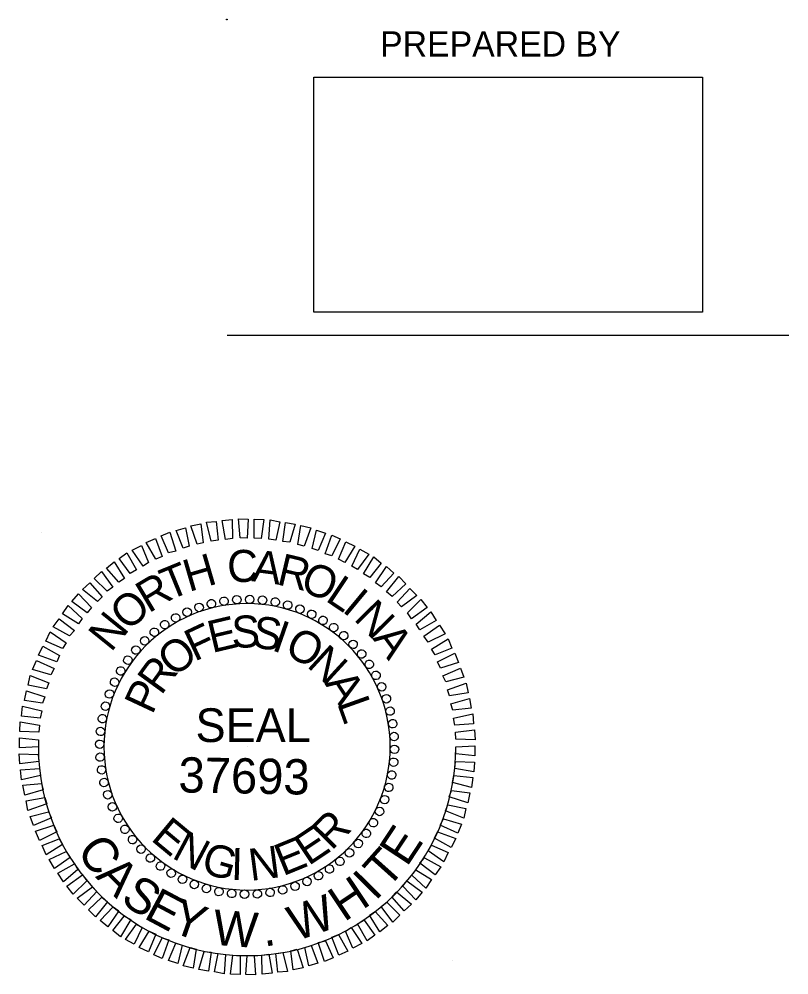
# Model space of a CAD drawing. Extents: x 2.6 to 3.27, y 0.03 to 1.77.
# Drawn here: x 3.0401 to 3.2685, y 1.3982 to 1.6817 of the extents above; entities that cross this region are included whole.
import ezdxf

# ---------------------------------------------------------------- set-up
doc = ezdxf.new("R2010")
doc.units = 0
for name, color, linetype in [('Draft_RDY_Construction_Class_Element', 7, 'Continuous'), ('Scratch_Level_2', 7, 'Continuous'), ('Sheet_PE_Note_CELL', 7, 'Continuous'), ('Sheet_Plan_CELL', 7, 'Continuous')]:
    doc.layers.add(name, color=color, linetype=linetype)

msp = doc.modelspace()

# ---------------------------------------------------------------- linework, layer by layer
at = {"layer": 'Draft_RDY_Construction_Class_Element'}
for p, q in [((3.12757, 1.66449), (3.24285, 1.66449)), ((3.12757, 1.59473), (3.12757, 1.66449)), ((3.24285, 1.66449), (3.24285, 1.59473)), ((3.24285, 1.59473), (3.12757, 1.59473))]:
    msp.add_line(p, q, dxfattribs=at)
msp.add_circle((3.10177, 1.68157), 0.0001, dxfattribs=at)
at = {"layer": 'Scratch_Level_2'}
for p, q in [((3.04683, 1.52933), (3.04683, 1.52933)), ((3.10777, 1.46583), (3.10777, 1.46583)), ((3.16871, 1.40233), (3.16871, 1.40233))]:
    msp.add_line(p, q, dxfattribs=at)
for radius, start, end in [(0.04247, 0, 180), (0.06193, 180, 0), (0.04247, 180, 0)]:
    msp.add_arc((3.10777, 1.46583), radius, start, end, dxfattribs=at)
at = {"layer": 'Sheet_PE_Note_CELL'}
for p, q in [((3.09713, 1.50828), (3.09713, 1.50828)), ((3.10097, 1.50898), (3.10097, 1.50898)), ((3.10472, 1.5095), (3.10472, 1.5095)), ((3.10855, 1.50959), (3.10855, 1.50959)), ((3.11239, 1.50933), (3.11239, 1.50933)), ((3.11614, 1.50872), (3.11614, 1.50872)), ((3.08998, 1.50584), (3.08998, 1.50584)), ((3.09347, 1.50724), (3.09347, 1.50724)), ((3.1198, 1.50794), (3.1198, 1.50794)), ((3.12346, 1.50672), (3.12346, 1.50672)), ((3.08658, 1.5041), (3.08658, 1.5041)), ((3.12694, 1.50515), (3.12694, 1.50515)), ((3.13034, 1.5034), (3.13034, 1.5034)), ((3.08022, 1.49992), (3.08022, 1.49992)), ((3.08327, 1.50209), (3.08327, 1.50209)), ((3.13348, 1.50122), (3.13348, 1.50122)), ((3.07734, 1.4973), (3.07734, 1.4973)), ((3.13653, 1.49887), (3.13653, 1.49887)), ((3.07473, 1.4946), (3.07473, 1.4946)), ((3.13924, 1.49625), (3.13924, 1.49625)), ((3.07238, 1.49155), (3.07238, 1.49155)), ((3.14185, 1.49338), (3.14185, 1.49338)), ((3.0702, 1.48841), (3.0702, 1.48841)), ((3.14403, 1.49033), (3.14403, 1.49033)), ((3.14604, 1.48701), (3.14604, 1.48701)), ((3.06845, 1.48501), (3.06845, 1.48501)), ((3.14778, 1.48361), (3.14778, 1.48361)), ((3.06688, 1.48152), (3.06688, 1.48152)), ((3.14917, 1.48013), (3.14917, 1.48013)), ((3.06566, 1.47786), (3.06566, 1.47786)), ((3.06488, 1.4742), (3.06488, 1.4742)), ((3.15022, 1.47647), (3.15022, 1.47647)), ((3.15092, 1.47263), (3.15092, 1.47263)), ((3.06427, 1.47045), (3.06427, 1.47045)), ((3.15144, 1.46888), (3.15144, 1.46888)), ((3.06401, 1.46662), (3.06401, 1.46662)), ((3.06409, 1.46278), (3.06409, 1.46278)), ((3.15153, 1.46505), (3.15153, 1.46505)), ((3.15127, 1.46121), (3.15127, 1.46121)), ((3.06462, 1.45903), (3.06462, 1.45903)), ((3.15066, 1.45746), (3.15066, 1.45746)), ((3.06531, 1.4552), (3.06531, 1.4552)), ((3.06636, 1.45154), (3.06636, 1.45154)), ((3.14987, 1.4538), (3.14987, 1.4538)), ((3.14865, 1.45014), (3.14865, 1.45014)), ((3.06776, 1.44805), (3.06776, 1.44805)), ((3.14708, 1.44665), (3.14708, 1.44665)), ((3.0695, 1.44465), (3.0695, 1.44465)), ((3.14534, 1.44325), (3.14534, 1.44325)), ((3.0715, 1.44134), (3.0715, 1.44134)), ((3.14316, 1.44012), (3.14316, 1.44012)), ((3.07368, 1.43829), (3.07368, 1.43829)), ((3.0763, 1.43541), (3.0763, 1.43541)), ((3.14081, 1.43706), (3.14081, 1.43706)), ((3.079, 1.43279), (3.079, 1.43279)), ((3.13531, 1.43175), (3.13531, 1.43175)), ((3.13819, 1.43436), (3.13819, 1.43436)), ((3.08205, 1.43044), (3.08205, 1.43044)), ((3.13226, 1.42957), (3.13226, 1.42957)), ((3.08519, 1.42826), (3.08519, 1.42826)), ((3.08859, 1.42652), (3.08859, 1.42652)), ((3.12895, 1.42756), (3.12895, 1.42756)), ((3.09208, 1.42495), (3.09208, 1.42495)), ((3.09574, 1.42373), (3.09574, 1.42373)), ((3.1184, 1.42338), (3.1184, 1.42338)), ((3.12206, 1.42442), (3.12206, 1.42442)), ((3.12555, 1.42582), (3.12555, 1.42582)), ((3.0994, 1.42294), (3.0994, 1.42294)), ((3.10315, 1.42233), (3.10315, 1.42233)), ((3.10698, 1.42207), (3.10698, 1.42207)), ((3.11082, 1.42216), (3.11082, 1.42216)), ((3.11457, 1.42268), (3.11457, 1.42268))]:
    msp.add_line(p, q, dxfattribs=at)
for points in [[(3.09295, 1.52589), (3.09112, 1.53138), (3.09408, 1.53199), (3.09478, 1.52633)], [(3.09713, 1.52685), (3.09574, 1.53243), (3.09861, 1.53269), (3.09922, 1.52711)], [(3.10132, 1.52737), (3.10036, 1.53295), (3.10332, 1.5333), (3.10341, 1.52764)], [(3.10568, 1.52781), (3.10524, 1.53348), (3.10812, 1.53339), (3.10777, 1.52772)], [(3.10986, 1.52772), (3.10986, 1.53339), (3.11274, 1.5333), (3.11195, 1.52764)], [(3.11422, 1.52746), (3.11457, 1.53313), (3.11744, 1.53261), (3.11631, 1.52711)], [(3.1184, 1.52676), (3.11919, 1.53234), (3.12206, 1.53191), (3.12049, 1.5265)], [(3.12285, 1.52581), (3.12372, 1.53147), (3.12668, 1.53077), (3.12468, 1.52537)], [(3.08449, 1.52336), (3.08223, 1.52842), (3.08484, 1.52947), (3.08667, 1.52389)], [(3.08876, 1.52476), (3.08676, 1.52999), (3.08946, 1.53077), (3.09059, 1.52537)], [(3.12703, 1.52467), (3.12834, 1.53008), (3.13104, 1.52921), (3.12886, 1.52406)], [(3.13095, 1.5231), (3.13296, 1.5286), (3.1354, 1.52755), (3.13296, 1.52249)], [(3.07691, 1.51944), (3.07368, 1.52415), (3.07639, 1.52554), (3.07856, 1.52049)], [(3.08066, 1.52153), (3.07787, 1.52642), (3.08057, 1.52764), (3.08257, 1.52232)], [(3.13488, 1.52145), (3.13706, 1.52659), (3.13976, 1.52537), (3.1368, 1.52049)], [(3.07307, 1.51726), (3.06985, 1.52171), (3.07211, 1.52336), (3.07499, 1.51831)], [(3.13889, 1.51944), (3.14124, 1.52441), (3.14386, 1.52293), (3.14054, 1.5184)], [(3.06976, 1.51465), (3.06601, 1.51883), (3.06837, 1.52066), (3.07142, 1.51578)], [(3.14229, 1.51709), (3.14534, 1.52214), (3.1476, 1.52031), (3.14421, 1.51604)], [(3.06627, 1.51195), (3.06244, 1.51578), (3.06453, 1.51787), (3.06793, 1.51317)], [(3.14586, 1.51447), (3.14909, 1.51927), (3.15135, 1.51735), (3.14752, 1.51325)], [(3.0634, 1.50889), (3.05895, 1.51247), (3.06113, 1.51447), (3.06479, 1.51029)], [(3.14917, 1.51177), (3.15275, 1.5163), (3.15484, 1.51421), (3.15083, 1.51046)], [(3.06035, 1.50558), (3.05581, 1.50898), (3.05773, 1.51125), (3.06157, 1.50715)], [(3.15231, 1.50872), (3.15606, 1.51282), (3.15815, 1.51072), (3.15362, 1.50733)], [(3.15536, 1.50558), (3.15937, 1.5095), (3.1612, 1.50715), (3.15658, 1.50384)], [(3.05773, 1.50227), (3.05302, 1.50523), (3.05468, 1.50776), (3.05886, 1.50393)], [(3.15798, 1.50218), (3.16225, 1.50584), (3.16391, 1.50332), (3.15902, 1.50053)], [(3.05512, 1.49878), (3.05023, 1.5014), (3.05198, 1.50384), (3.05651, 1.50035)], [(3.05302, 1.49503), (3.04805, 1.49721), (3.04936, 1.49992), (3.05407, 1.49669)], [(3.16024, 1.49861), (3.16486, 1.50192), (3.16652, 1.49931), (3.16147, 1.49686)], [(3.16251, 1.49477), (3.16739, 1.49782), (3.16853, 1.49512), (3.16356, 1.49312)], [(3.05128, 1.49102), (3.04588, 1.49303), (3.04718, 1.49573), (3.05215, 1.49294)], [(3.04954, 1.48719), (3.04413, 1.48876), (3.04526, 1.49146), (3.0505, 1.48902)], [(3.16425, 1.49102), (3.1694, 1.49364), (3.17053, 1.49085), (3.16513, 1.48911)], [(3.16582, 1.48693), (3.17114, 1.48919), (3.1721, 1.48649), (3.1667, 1.4851)], [(3.04823, 1.483), (3.04282, 1.48414), (3.04343, 1.48701), (3.04893, 1.48483)], [(3.16722, 1.48274), (3.1728, 1.48475), (3.17332, 1.48187), (3.16783, 1.48091)], [(3.0471, 1.47882), (3.04169, 1.47952), (3.0423, 1.48248), (3.04779, 1.48065)], [(3.16826, 1.47856), (3.17376, 1.48021), (3.17428, 1.47725), (3.16879, 1.47673)], [(3.0464, 1.47437), (3.04082, 1.4749), (3.04117, 1.47786), (3.04683, 1.47647)], [(3.16905, 1.47437), (3.17472, 1.47559), (3.17498, 1.47263), (3.1694, 1.47228)], [(3.04596, 1.47019), (3.0403, 1.47036), (3.04047, 1.47324), (3.04614, 1.47228)], [(3.04588, 1.46583), (3.04021, 1.46557), (3.04021, 1.46853), (3.04588, 1.46792)], [(3.16957, 1.47019), (3.17524, 1.47089), (3.17541, 1.46792), (3.16975, 1.4681)], [(3.16966, 1.46583), (3.17533, 1.46609), (3.17533, 1.46313), (3.16966, 1.46374)], [(3.04596, 1.46147), (3.0403, 1.46078), (3.04012, 1.46374), (3.04579, 1.46356)], [(3.16957, 1.46147), (3.17524, 1.4613), (3.17506, 1.45842), (3.1694, 1.45938)], [(3.04649, 1.45729), (3.04082, 1.45607), (3.04056, 1.45903), (3.04614, 1.45938)], [(3.16914, 1.45729), (3.17472, 1.45677), (3.17437, 1.4538), (3.1687, 1.4552)], [(3.04727, 1.4531), (3.04178, 1.45145), (3.04125, 1.45441), (3.04675, 1.45493)], [(3.16844, 1.45284), (3.17384, 1.45215), (3.17323, 1.44918), (3.16774, 1.45101)], [(3.04832, 1.44892), (3.04274, 1.44692), (3.04221, 1.44979), (3.04771, 1.45075)], [(3.16731, 1.44866), (3.17271, 1.44753), (3.1721, 1.44465), (3.16661, 1.44683)], [(3.04971, 1.44474), (3.04439, 1.44247), (3.04343, 1.44517), (3.04884, 1.44657)], [(3.166, 1.44447), (3.1714, 1.44291), (3.17027, 1.4402), (3.16504, 1.44264)], [(3.05128, 1.44064), (3.04614, 1.43802), (3.045, 1.44081), (3.05041, 1.44256)], [(3.16425, 1.44064), (3.16966, 1.43863), (3.16835, 1.43593), (3.16338, 1.43872)], [(3.05302, 1.43689), (3.04814, 1.43384), (3.04701, 1.43654), (3.05198, 1.43855)], [(3.05529, 1.43305), (3.05067, 1.42974), (3.04901, 1.43236), (3.05407, 1.4348)], [(3.16251, 1.43663), (3.16748, 1.43445), (3.16617, 1.43175), (3.16147, 1.43497)], [(3.16042, 1.43288), (3.1653, 1.43027), (3.16356, 1.42782), (3.15902, 1.43131)], [(3.05756, 1.42948), (3.05328, 1.42582), (3.05163, 1.42835), (3.05651, 1.43114)], [(3.1578, 1.42939), (3.16251, 1.42643), (3.16085, 1.4239), (3.15667, 1.42774)], [(3.06017, 1.42608), (3.05616, 1.42216), (3.05433, 1.42451), (3.05895, 1.42782)], [(3.15519, 1.42608), (3.15972, 1.42268), (3.1578, 1.42041), (3.15397, 1.42451)], [(3.06322, 1.42294), (3.05947, 1.41885), (3.05738, 1.42094), (3.06191, 1.42434)], [(3.06636, 1.41989), (3.06279, 1.41536), (3.06069, 1.41745), (3.0647, 1.4212)], [(3.15214, 1.42277), (3.15658, 1.41919), (3.1544, 1.41719), (3.15074, 1.42137)], [(3.06967, 1.41719), (3.06645, 1.4124), (3.06418, 1.41431), (3.06802, 1.41841)], [(3.14926, 1.41972), (3.1531, 1.41588), (3.151, 1.41379), (3.1476, 1.4185)], [(3.07325, 1.41457), (3.0702, 1.40952), (3.06793, 1.41135), (3.07133, 1.41562)], [(3.14577, 1.41702), (3.14952, 1.41283), (3.14717, 1.411), (3.14412, 1.41588)], [(3.07665, 1.41222), (3.07429, 1.40725), (3.07168, 1.40873), (3.07499, 1.41327)], [(3.13863, 1.41222), (3.14185, 1.40751), (3.13915, 1.40612), (3.13697, 1.41117)], [(3.14246, 1.4144), (3.14569, 1.40995), (3.14342, 1.4083), (3.14054, 1.41335)], [(3.08066, 1.41022), (3.07848, 1.40507), (3.07578, 1.40629), (3.07874, 1.41117)], [(3.08458, 1.40856), (3.08257, 1.40307), (3.08013, 1.40411), (3.08257, 1.40917)], [(3.13488, 1.41013), (3.13767, 1.40525), (3.13496, 1.40403), (3.13296, 1.40934)], [(3.0885, 1.40699), (3.08719, 1.40159), (3.08449, 1.40246), (3.08667, 1.4076)], [(3.09269, 1.40586), (3.09181, 1.40019), (3.08885, 1.40089), (3.09086, 1.40629)], [(3.12677, 1.4069), (3.12878, 1.40167), (3.12607, 1.40089), (3.12494, 1.40629)], [(3.13104, 1.4083), (3.13331, 1.40324), (3.13069, 1.4022), (3.12886, 1.40777)], [(3.09713, 1.4049), (3.09635, 1.39932), (3.09347, 1.39976), (3.09504, 1.40516)], [(3.10132, 1.4042), (3.10097, 1.39853), (3.09809, 1.39906), (3.09922, 1.40455)], [(3.10568, 1.40394), (3.10568, 1.39827), (3.1028, 1.39836), (3.10358, 1.40403)], [(3.10986, 1.40385), (3.1103, 1.39819), (3.10742, 1.39827), (3.10777, 1.40394)], [(3.11422, 1.40429), (3.11518, 1.39871), (3.11221, 1.39836), (3.11213, 1.40403)], [(3.1184, 1.40481), (3.1198, 1.39923), (3.11692, 1.39897), (3.11631, 1.40455)], [(3.12259, 1.40577), (3.12442, 1.40028), (3.12145, 1.39967), (3.12076, 1.40533)]]:
    msp.add_lwpolyline(points, close=True, dxfattribs=at)
for centre, major_axis in [((3.09353, 1.50717), (-0.00041, 0.00119)), ((3.09719, 1.50826), (-0.0003, 0.00122)), ((3.10093, 1.50902), (-0.0002, 0.00124)), ((3.10472, 1.50945), (-0.00009, 0.00125)), ((3.10853, 1.50955), (0.00002, 0.00126)), ((3.11234, 1.50932), (0.00013, 0.00125)), ((3.11611, 1.50875), (0.00024, 0.00123)), ((3.11982, 1.50786), (0.00035, 0.00121)), ((3.08657, 1.50407), (-0.00061, 0.0011)), ((3.08998, 1.50578), (-0.00051, 0.00115)), ((3.12344, 1.50665), (0.00045, 0.00117)), ((3.12694, 1.50513), (0.00055, 0.00113)), ((3.08332, 1.50208), (-0.0007, 0.00104)), ((3.13029, 1.50331), (0.00065, 0.00108)), ((3.13347, 1.50121), (0.00074, 0.00102)), ((3.08025, 1.49981), (-0.00079, 0.000976)), ((3.13645, 1.49883), (0.000824, 0.000947)), ((3.07739, 1.49728), (-0.000872, 0.000903)), ((3.13922, 1.49621), (0.000903, 0.000872)), ((3.07477, 1.49452), (-0.000947, 0.000824)), ((3.14175, 1.49335), (0.000976, 0.00079)), ((3.07239, 1.49153), (-0.00102, 0.00074)), ((3.14402, 1.49028), (0.00104, 0.0007)), ((3.07029, 1.48835), (-0.00108, 0.00065)), ((3.14601, 1.48703), (0.0011, 0.00061)), ((3.06847, 1.485), (-0.00113, 0.00055)), ((3.06695, 1.4815), (-0.00117, 0.00045)), ((3.14771, 1.48362), (0.00115, 0.00051)), ((3.14911, 1.48007), (0.00119, 0.00041)), ((3.06574, 1.47788), (-0.00121, 0.00035)), ((3.15019, 1.47641), (0.00122, 0.0003)), ((3.06485, 1.47417), (-0.00123, 0.00024)), ((3.06428, 1.4704), (-0.00125, 0.00013)), ((3.15095, 1.47267), (0.00124, 0.0002)), ((3.15139, 1.46888), (0.00125, 0.00009)), ((3.06405, 1.46659), (-0.00126, 0.00002)), ((3.15149, 1.46507), (0.00126, -0.00002)), ((3.06415, 1.46278), (-0.00125, -0.00009)), ((3.06458, 1.45899), (-0.00124, -0.0002)), ((3.15125, 1.46126), (0.00125, -0.00013)), ((3.15069, 1.45749), (0.00123, -0.00024)), ((3.06534, 1.45525), (-0.00122, -0.0003)), ((3.1498, 1.45378), (0.00121, -0.00035)), ((3.06642, 1.4516), (-0.00119, -0.00041)), ((3.14859, 1.45016), (0.00117, -0.00045)), ((3.06782, 1.44805), (-0.00115, -0.00051)), ((3.06952, 1.44463), (-0.0011, -0.00061)), ((3.14707, 1.44666), (0.00113, -0.00055)), ((3.14525, 1.44331), (0.00108, -0.00065)), ((3.07152, 1.44138), (-0.00104, -0.0007)), ((3.14314, 1.44013), (0.00102, -0.00074)), ((3.07379, 1.43831), (-0.000976, -0.00079)), ((3.14077, 1.43714), (0.000947, -0.000824)), ((3.07631, 1.43546), (-0.000903, -0.000872)), ((3.13814, 1.43438), (0.000872, -0.000903)), ((3.07908, 1.43283), (-0.000824, -0.000947)), ((3.08207, 1.43046), (-0.00074, -0.00102)), ((3.13528, 1.43185), (0.00079, -0.000976)), ((3.08525, 1.42835), (-0.00065, -0.00108)), ((3.12897, 1.42759), (0.00061, -0.0011)), ((3.13222, 1.42958), (0.0007, -0.00104)), ((3.0886, 1.42653), (-0.00055, -0.00113)), ((3.0921, 1.42501), (-0.00045, -0.00117)), ((3.12555, 1.42589), (0.00051, -0.00115)), ((3.09571, 1.4238), (-0.00035, -0.00121)), ((3.09942, 1.42291), (-0.00024, -0.00123)), ((3.1032, 1.42235), (-0.00013, -0.00125)), ((3.107, 1.42211), (-0.00002, -0.00126)), ((3.11082, 1.42221), (0.00009, -0.00125)), ((3.11461, 1.42264), (0.0002, -0.00124)), ((3.11835, 1.4234), (0.0003, -0.00122)), ((3.122, 1.42449), (0.00041, -0.00119))]:
    msp.add_ellipse(centre, major_axis=major_axis, ratio=0.999708, dxfattribs=at)
at = {"layer": 'Sheet_Plan_CELL'}
msp.add_line((3.26853, 1.58781), (3.10187, 1.58781), dxfattribs=at)

# ---------------------------------------------------------------- texts
at = {"layer": 'Sheet_PE_Note_CELL'}
for s, height, rotation, p in [('H', 0.0095, 16.2881, (3.09049, 1.51173)), ('C', 0.0095, 1.4832, (3.10197, 1.5146)), ('A', 0.0095, 352.5864, (3.10894, 1.51499)), ('R', 0.0095, 346.666, (3.11626, 1.51407)), ('T', 0.0095, 22.179, (3.0845, 1.50915)), ('O', 0.0095, 337.821, (3.12309, 1.51239)), ('R', 0.0095, 30.9582, (3.07855, 1.50533)), ('L', 0.0095, 326.1343, (3.1307, 1.50933)), ('O', 0.0095, 42.5191, (3.07249, 1.49983)), ('I', 0.0095, 320.353, (3.13568, 1.5062)), ('N', 0.0095, 314.6222, (3.13915, 1.50365)), ('N', 0.0095, 51.0517, (3.06739, 1.49366)), ('F', 0.0095, 25.1139, (3.09217, 1.49103)), ('E', 0.0095, 13.334, (3.09736, 1.49362)), ('S', 0.0095, 1.4832, (3.10324, 1.49517)), ('S', 0.0095, 352.5864, (3.10902, 1.49536)), ('I', 0.0095, 340.7633, (3.11475, 1.49458)), ('O', 0.0095, 331.9594, (3.11844, 1.49351)), ('A', 0.0095, 306.1346, (3.14483, 1.49799)), ('O', 0.0095, 39.647, (3.08618, 1.48618)), ('N', 0.0095, 317.4809, (3.1252, 1.4898)), ('R', 0.0095, 53.8654, (3.08228, 1.48086)), ('P', 0.0095, 64.9491, (3.07961, 1.47512)), ('A', 0.0095, 303.3373, (3.13066, 1.4846)), ('L', 0.0095, 289.6205, (3.13441, 1.47878)), ('37693', 0.010461, 359, (3.08735, 1.45232)), ('R', 0.0095, 45.3778, (3.13283, 1.43484)), ('E', 0.0095, 320.353, (3.07891, 1.43831)), ('N', 0.0095, 331.9594, (3.08513, 1.43302)), ('E', 0.0095, 33.8657, (3.126, 1.43037)), ('E', 0.01046, 56.6627, (3.15516, 1.42998)), ('C', 0.01046, 306.1346, (3.0569, 1.43494)), ('E', 0.0095, 22.179, (3.1184, 1.42739)), ('G', 0.0095, 343.7119, (3.09372, 1.42867)), ('I', 0.0095, 358.5168, (3.10292, 1.42634)), ('N', 0.0095, 7.4136, (3.10884, 1.42603)), ('T', 0.01046, 48.2222, (3.14933, 1.42335)), ('A', 0.01046, 314.6222, (3.06257, 1.42721)), ('I', 0.01046, 45.3778, (3.14577, 1.41992)), ('S', 0.01046, 326.1343, (3.06986, 1.41986)), ('H', 0.01046, 33.8657, (3.13657, 1.41374)), ('E', 0.01046, 331.9594, (3.07677, 1.41515)), ('Y', 0.01046, 340.7633, (3.08463, 1.4111)), ('W', 0.01046, 19.2367, (3.12219, 1.40806)), ('W', 0.01046, 355.5509, (3.09738, 1.40716)), ('.', 0.01046, 10.3755, (3.11284, 1.40648))]:
    msp.add_text(s, height=height, rotation=rotation, dxfattribs=at).set_placement(p)
msp.add_text('SEAL', height=0.01, dxfattribs=at).set_placement((3.09248, 1.46725))
at = {"layer": 'Sheet_Plan_CELL'}
msp.add_text('PREPARED BY', height=0.0075, rotation=0, dxfattribs=at).set_placement((3.14724, 1.67055))

doc.saveas('drawing.dxf')
